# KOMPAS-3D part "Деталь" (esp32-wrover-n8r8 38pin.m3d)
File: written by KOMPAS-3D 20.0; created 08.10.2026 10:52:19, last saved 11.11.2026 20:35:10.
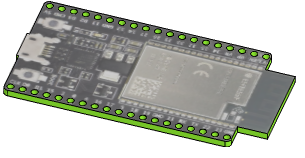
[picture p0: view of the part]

Document properties: Полное имя файла: D:\myProjects\Progect_esp32\box_compas\esp32\esp32-wrover-n8r8 38pin.m3d

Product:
- Part/product: Деталь
    Масса: 0.016388

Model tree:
1. Эскиз:1
2. Элемент выдавливания:1
     Расстояние 1 = 1.5
3. Эскиз:2  (with: Элемент выдавливания:1)
4. Элемент выдавливания:3
     Расстояние 2 = 1.5
5. Эскиз:3  (with: Элемент выдавливания:1)
6. Элемент выдавливания:4
     Расстояние 2 = 1.5
7. Массив по сетке:1  (with: Элемент выдавливания:4, Эскиз:3)  (44 pattern instances)
     Шаг 1 = 25.4; Угол раствора = -90; Шаг 2 = 2.54
8. Скругление:1  (with: Элемент выдавливания:3, Элемент выдавливания:1)
     Радиус = 1

Referenced files in D:\myProjects\Progect_esp32\box_compas\esp32\: esp32-wrover-n86r8.png
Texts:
  esp32-wrover-n86r8.png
